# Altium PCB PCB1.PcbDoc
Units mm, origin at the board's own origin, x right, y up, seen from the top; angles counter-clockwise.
Board outline 50 x 50 mm, 2 copper layers (Top Layer, Bottom Layer); 47 components, 35 nets, 150 pads, 6 vias.
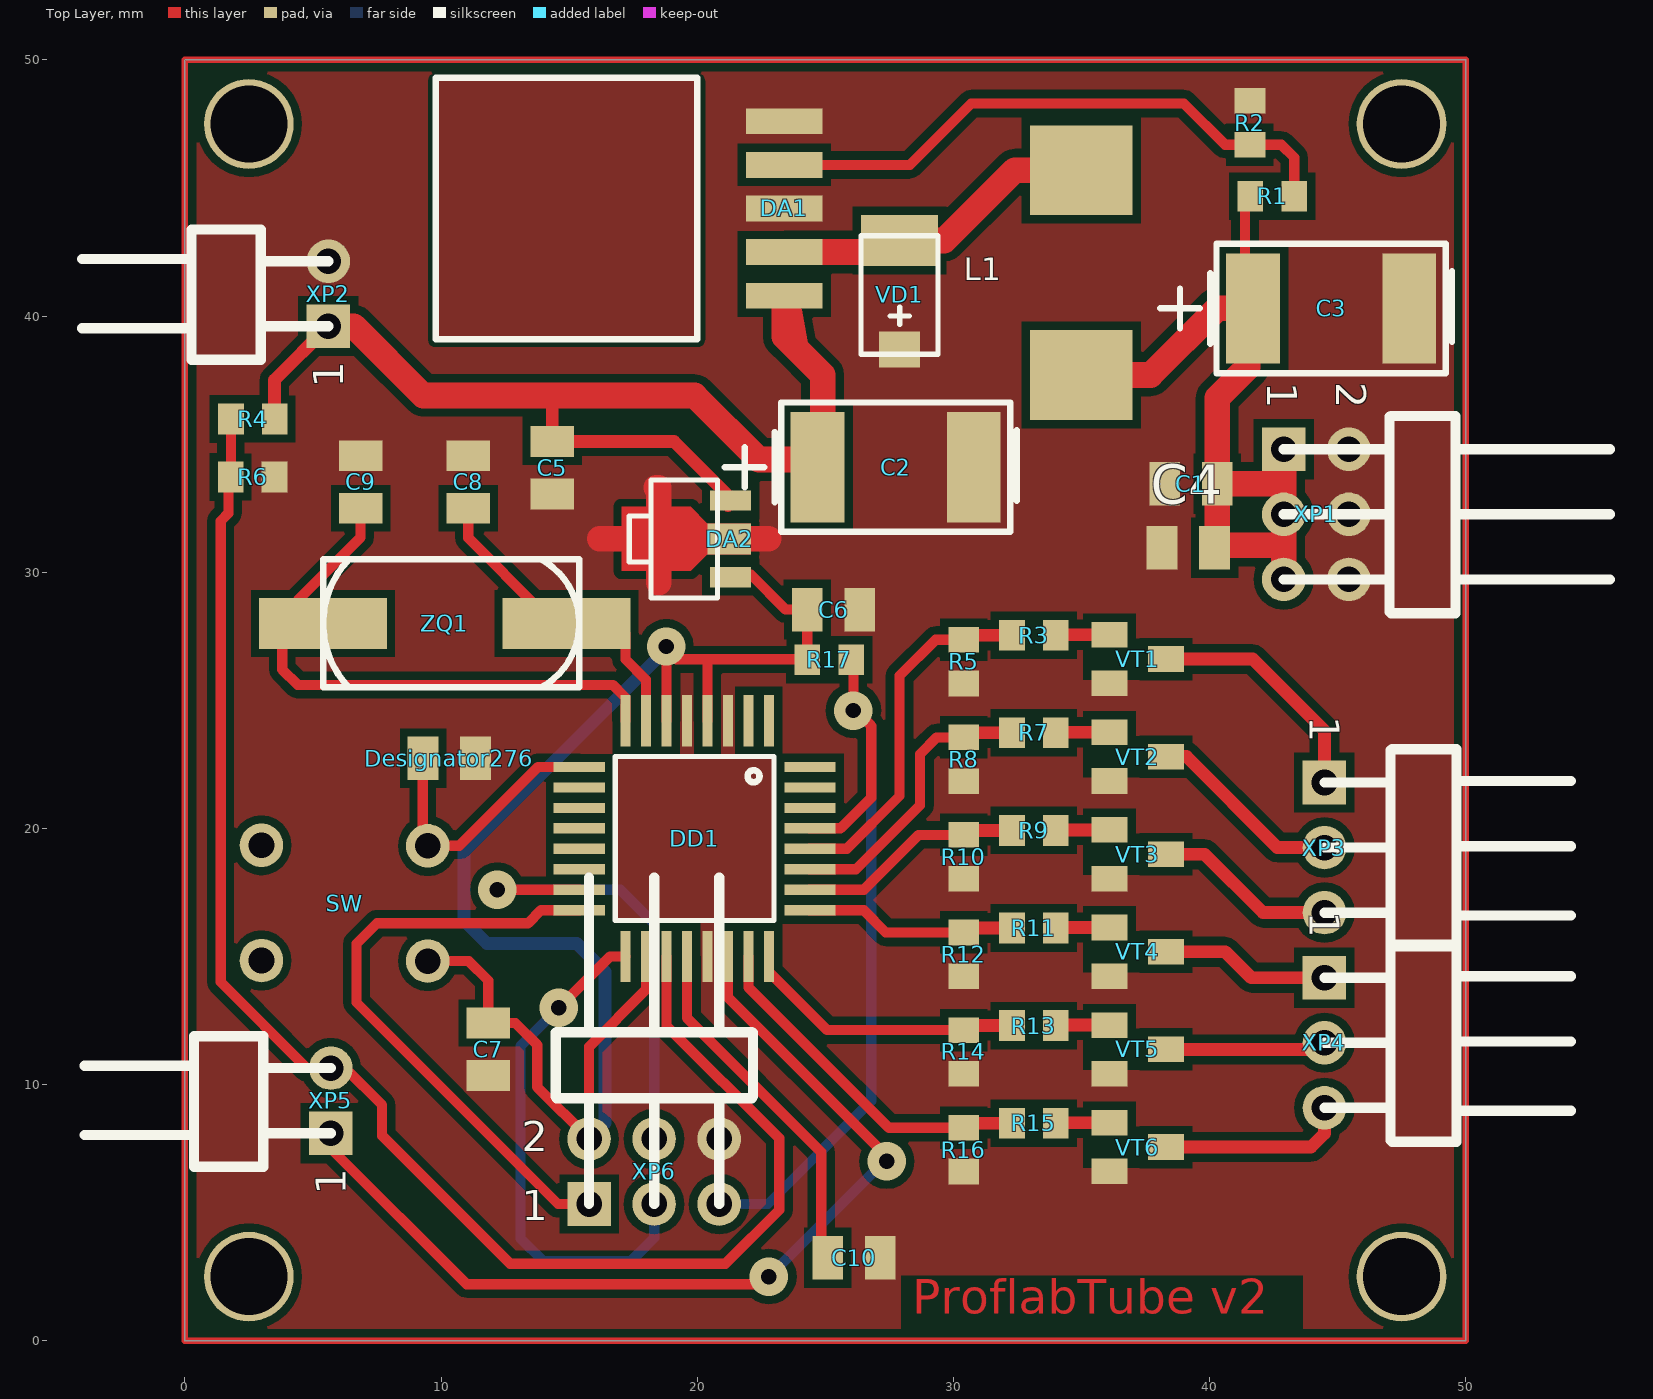
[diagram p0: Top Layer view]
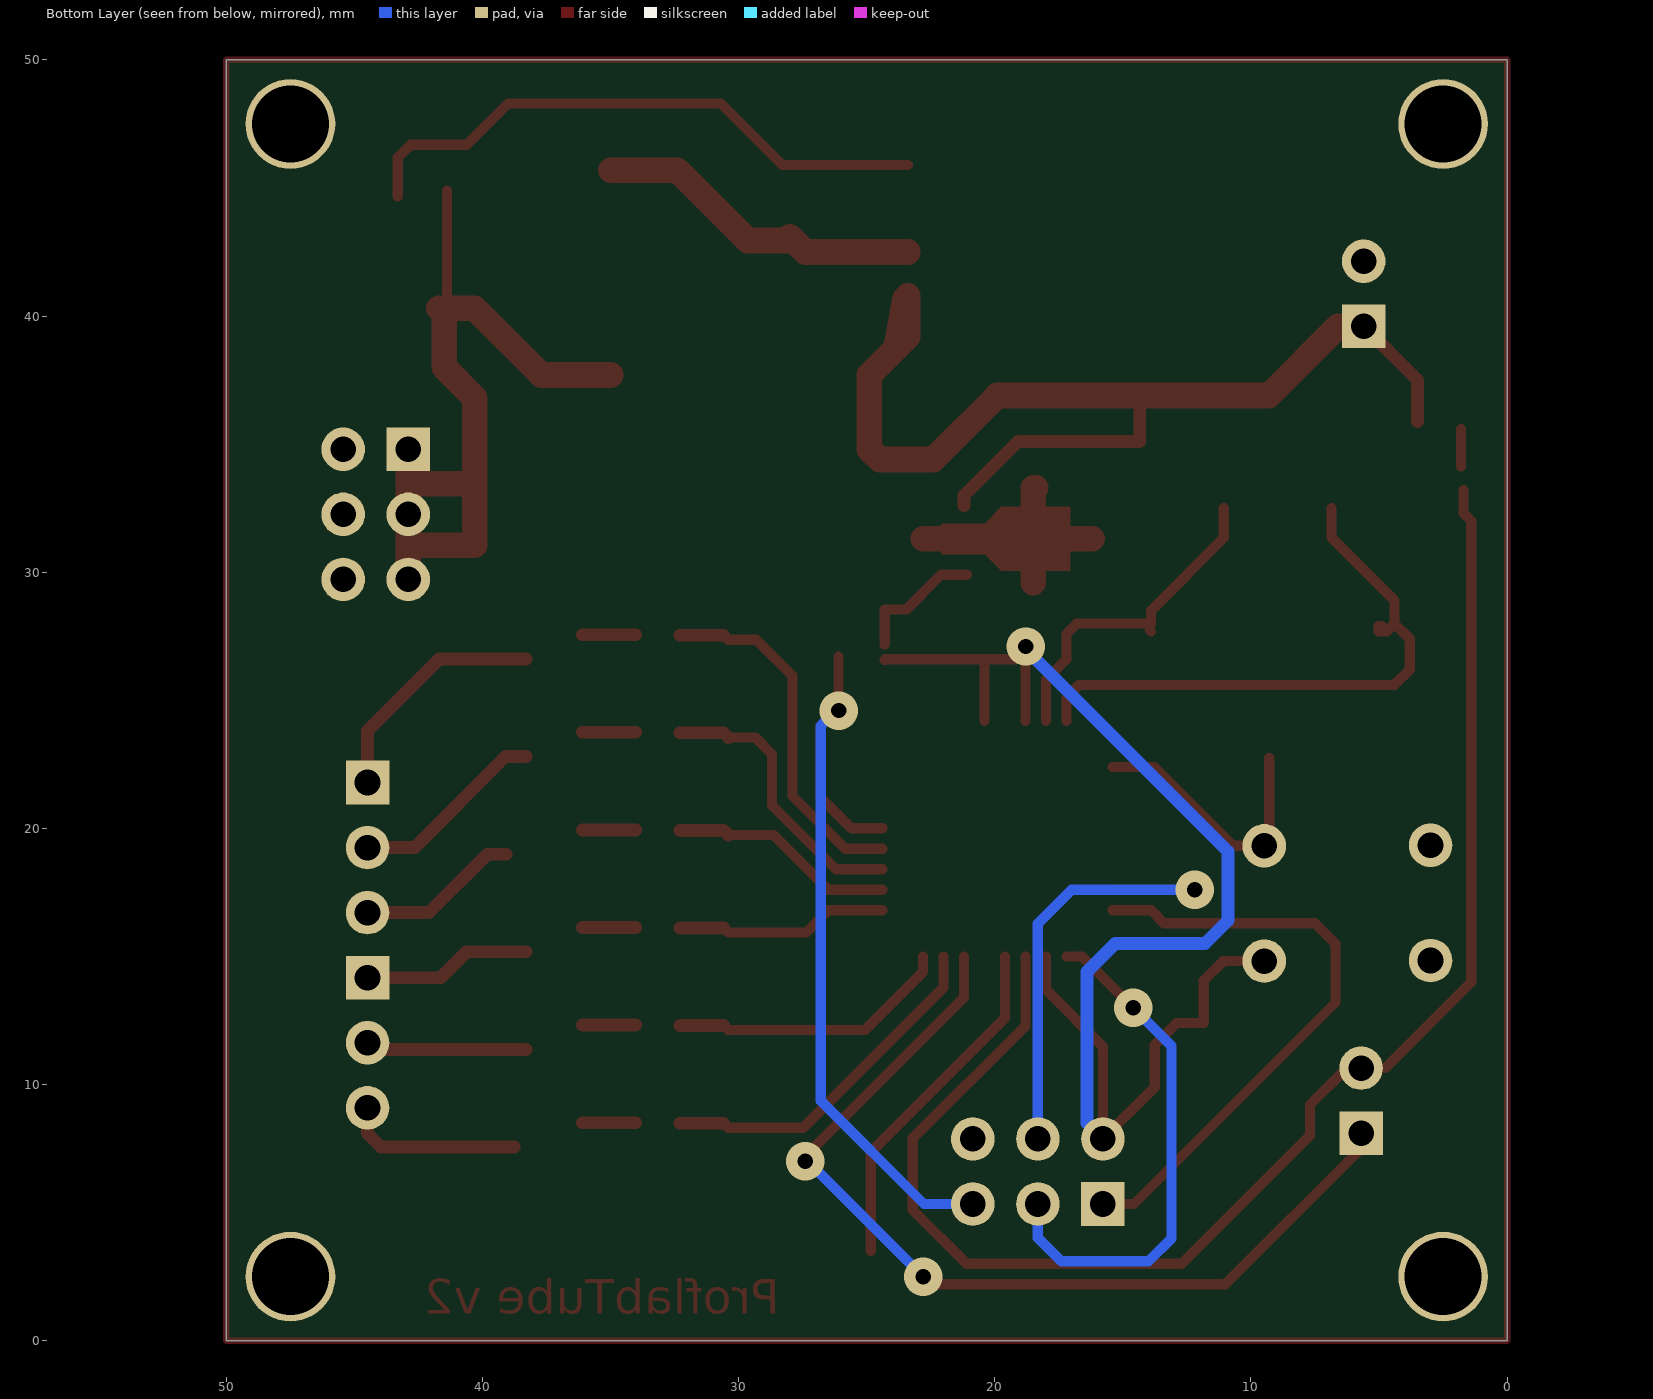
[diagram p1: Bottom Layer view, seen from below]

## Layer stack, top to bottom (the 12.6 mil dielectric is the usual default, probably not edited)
Top Layer: signal copper 0.0356
Dielectric: dielectric 0.32, FR-4, Dk 4.8
Bottom Layer: signal copper 0.0356

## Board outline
0,0 50,0 50,50 0,50

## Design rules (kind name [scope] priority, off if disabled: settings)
Clearance [All] p1: gap=0.32
PolygonConnect PolygonConnect_1 [All vs IsNamedPolygon('Top Layer-No Net')] p1: connectstyle=Direct reliefconductorwidth=0.254 reliefentries=4 polygonreliefangle="90 Angle" airgapwidth=0.254
PolygonConnect [All] p2: connectstyle=Relief reliefconductorwidth=0.254 reliefentries=4 polygonreliefangle="90 Angle" airgapwidth=0.254
RoutingVias [All] p1: holewidth=0.711 width=1.7 viastyle="Through Hole" minholewidth=0.711 minwidth=1.27 maxholewidth=0.711 maxwidth=1.27
SilkscreenOverComponentPads [All] p1: minsilkscreentomaskgap=0.254
SolderMaskExpansion [All] p1: expansion=0.102
Width [All] p1: maxlimit=1 minlimit=0.25 preferedwidth=0.3
27 further rules are at their usual default settings.

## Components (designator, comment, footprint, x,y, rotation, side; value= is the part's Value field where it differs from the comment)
C1 "C0805" SMD0805 40.3,33.4 r180 top
C2 "TAJ_SMD_E" FT-SMD-E 24.7,34.1 r0 top
C3 "TAJ_SMD_E" FT-SMD-E 41.7,40.3 r0 top
C4 "C0805" SMD0805 40.2,30.9 r180 top
C5 "C0805" SMD0805 14.4,35.1 r270 top
C6 "C0805" SMD0805 24.3,28.6 r0 top
C7 "C0805" SMD0805 11.9,12.4 r270 top
C8 "C0805" SMD0805 11,32.5 r90 top
C9 "C0805" SMD0805 6.8,32.5 r90 top
C10 "C0805" SMD0805 25.1,3.3 r0 top
DA1 "LM2576" "TO_220-5 smd" 23.4,40.8 r90 top
DA2 "TA78L05_F" SOT-89 21.3,29.8 r90 top
DD1 "ATmega328" Quad32 22.8,24.2 r270 top
Designator276 "Comment" SMD0805 9.3,22.8 r0 top
L1 "Comment" 7443552560 35,41.7 r90 top
R1 "R0603" SMD0603 41.6,44.7 r0 top
R2 "R0603" SMD0603 41.6,48.4 r270 top
R3 "R0603" SMD0603 32.29,27.56 r0 top
R4 "R0603" SMD0603 1.8,36 r0 top
R5 "R0603" SMD0603 30.385,25.655 r90 top
R6 "R0603" SMD0603 3.5,33.7 r180 top
R7 "R0603" SMD0603 32.29,23.75 r0 top
R8 "R0603" SMD0603 30.385,21.845 r90 top
R9 "R0603" SMD0603 32.29,19.94 r0 top
R10 "R0603" SMD0603 30.385,18.035 r90 top
R11 "R0603" SMD0603 32.29,16.13 r0 top
R12 "R0603" SMD0603 30.385,14.225 r90 top
R13 "R0603" SMD0603 32.29,12.32 r0 top
R14 "R0603" SMD0603 30.385,10.415 r90 top
R15 "R0603" SMD0603 32.29,8.51 r0 top
R16 "R0603" SMD0603 30.385,6.605 r90 top
R17 "R0603" SMD0603 24.3,26.6 r0 top
SW "Comment" "PT65-102 - duplicate" 6.8,16.8 r0 top
VD1 "10MQ040N" SMA 27.9,38.7 r90 top
VT1 "FDV303N" SOT23_FDV303N 37.2,26.61 r90 top
VT2 "FDV303N" SOT23_FDV303N 37.2,22.8 r90 top
VT3 "FDV303N" SOT23_FDV303N 37.2,18.99 r90 top
VT4 "FDV303N" SOT23_FDV303N 37.2,15.18 r90 top
VT5 "FDV303N" SOT23_FDV303N 37.2,11.37 r90 top
VT6 "FDV303N" SOT23_FDV303N 37.2,7.56 r90 top
XP1 "PLD_6R" PLD_6R 42.9,34.8 r270 top
XP2 "PLS_2R" PLS_2R 5.6,39.6 r90 top
XP3 "PLS_3R" PLS_3R 44.49,21.79 r270 top
XP4 "PLS_3R" PLS_3R 44.49,14.17 r270 top
XP5 "PLS_2R" PLS_2R 5.7,8.1 r90 top
XP6 "PLD_6R" PLD_6R 15.78,5.335 r0 top
ZQ1 "ZQ" HC49SM 5.4,28 r0 top

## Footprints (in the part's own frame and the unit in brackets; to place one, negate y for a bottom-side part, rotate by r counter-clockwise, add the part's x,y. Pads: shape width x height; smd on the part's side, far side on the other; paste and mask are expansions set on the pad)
7443552560 [mm]
  rect 3.5x4 smd: 1(-4,0) 2(4,0)
FT-SMD-E [mm]
  rect 2.1x4.3 smd: 1(0,0) 2(6.1,0)
  silkscreen extent -3.62,-2.53 7.77,2.53
HC49SM [mm]
  rect 5x2 smd: 1(0,0) 2(9.5,0)
  silkscreen extent 0,-2.5 10,2.5
PLD_6R [mm]
  rect 1.7x1.7 hole 1: 1(0,0)
  round 1.7 hole 1: 2(0,2.54) 3(2.54,0) 4(2.54,2.54) 5(5.08,0) 6(5.08,2.54)
  silkscreen extent -1.3,0 6.4,12.74
PLS_2R [mm]
  rect 1.7x1.7 hole 1: 1(0,0)
  round 1.7 hole 1: 2(2.54,0)
  silkscreen extent -1.31,0 3.78,9.62
PLS_3R [mm]
  rect 1.7x1.7 hole 1: 1(0,0)
  round 1.7 hole 1: 2(2.54,0) 3(5.08,0)
  silkscreen extent -1.3,0 6.4,9.62
"PT65-102 - duplicate" [mm]
  round 1.7 hole 1: 1(-3.81,2.54) 2(-3.81,-1.96) 3(2.682,-1.982) 4(2.682,2.518)
Quad32 [mm]
  rect 2x0.4 smd: 1(0,0) 2(0,-0.8) 3(0,-1.6) 4(0,-2.4) 5(0,-3.2) 6(0,-4) 7(0,-4.8) 8(0,-5.6) 17(9.2,-5.6) 18(9.2,-4.8) 19(9.2,-4) 20(9.2,-3.2) 21(9.2,-2.4) 22(9.2,-1.6) 23(9.2,-0.8) 24(9.2,0)
  rect 0.4x2 smd: 9(1.8,-7.4) 10(2.6,-7.4) 11(3.4,-7.4) 12(4.2,-7.4) 13(5,-7.4) 14(5.8,-7.4) 15(6.6,-7.4) 16(7.4,-7.4) 25(7.4,1.6) 26(6.6,1.6) 27(5.8,1.6) 28(5,1.6) 29(4.2,1.6) 30(3.4,1.6) 31(2.6,1.6) 32(1.8,1.6)
  silkscreen extent 1.4,-6 7.8,0.2
SMA [mm]
  rect 1.4x1.6 smd: 1(0,0)
  rect 2x3 smd: 2(4.25,0)
  silkscreen extent -0.19,-1.5 4.44,1.5
SMD0603 [mm]
  rect 1x1.2 smd: 1(0,-0.02) 2(1.71,-0.02)
SMD0805 [mm]
  rect 1.2x1.7 smd: 1(0,-0.06) 2(2.05,-0.06)
SOT23_FDV303N [mm]
  rect 1x1.4 smd: D(0,-1.1) G(0.95,1.1) S(-0.95,1.1)
  Top Layer pour cut-out: -0.8,-0.5 -0.8,2.125 0.8,2.125 0.8,-0.5
SOT-89 [mm]
  rect 0.8x1.6 smd: 1(0,0) 3(3,0)
  rect 1.2x1.7 smd: 2(1.5,0.05)
  Top Layer region: 2.1,-0.8 2.1,0.9 2.75,1.55 2.75,4.25 0.25,4.25 0.25,1.55 0.9,0.9 0.9,-0.8
  silkscreen extent -0.8,0.5 3.8,3.95
"TO_220-5 smd" [mm]
  rect 1x3 smd: 1(0,0) 2(1.7,0) 3(3.4,0) 4(5.1,0) 5(6.8,0)
  silkscreen extent -1.7,3.4 8.5,13.6

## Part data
VT1 VT2 VT3 VT4 VT5 VT6: "IGFET(P)"

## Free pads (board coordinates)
  round 3.5 hole 3: 4(2.5,2.5) 4(2.5,47.5) 4(47.5,2.5) 4(47.5,47.5)

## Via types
v1: diameter 1.5, hole 0.6, Top Layer to Bottom Layer, 6 vias

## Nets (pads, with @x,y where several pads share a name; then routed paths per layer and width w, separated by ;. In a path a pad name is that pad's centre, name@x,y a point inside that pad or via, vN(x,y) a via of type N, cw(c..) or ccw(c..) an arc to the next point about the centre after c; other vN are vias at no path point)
1: DD1.9 Designator276.1 SW.4 | length 10.8
  Top Layer w0.4: Designator276.1@9.282,22.74 9.282,19.318 SW.4 10.718,19.318 13.8,22.4 DD1.9
2: 
+5V: C6.1 C7.1 DA2.1 DD1.4 DD1.6 DD1.18 R17.1 SW.3 XP6.2 | length 63
  Top Layer w0.4: SW.3@9.282,14.818 SW.3 11.082,14.818 11.84,14.06 C7.1 12.9,12.4 13.755,11.545 13.755,9.9 XP6.2 15.78,11.48 18,13.7 DD1.18 ; v1@18.7,27.1 18.75,27.05 v1@18.85,26.95 ; DD1.6 18.8,26.9 v1@18.85,26.95 ; v1@19.08,27.18 v1@18.85,26.95 ; DD1.4 20.4,26.6 ; DA2.1@21.1,29.9 22.1,29.9 23.46,28.54 C6.1 24.3,27.18 ; R17.1 24.28,26.6 20.4,26.6 ; v1@18.85,26.95 19.2,26.6 20.4,26.6
  Bottom Layer w0.5: XP6.2 16.4,8.495 16.4,14.4 15.3,15.5 11.8,15.5 10.9,16.4 10.9,19.1 18.8,27 v1(18.8,27.1) v1@18.8,27.2
GND: C1.2 C2.2 C3.2 C4.2 C5.2 C6.2 C7.2 C8.2 C9.2 C10.2 DA1.3 DA1.5 DA2.2 DD1.3 DD1.5 DD1.21 Designator276.2 R2.1 R5.1 R6.1 R8.1 R10.1 R12.1 R14.1 R16.1 VD1.1 VT1.S VT2.S VT3.S VT4.S VT5.S VT6.S XP1.2 XP1.4 XP1.6 XP2.2 XP6.6 | length 7.6
  Top Layer w1: 16.2,31.3 18.5,31.3 ; 18.4,33.3 18.5,33.3 18.5,29.6 ; DA2.2 22.8,31.3
NetC1_1: C1.1 C3.1 C4.1 L1.1 R1.1 XP1.1 XP1.3 XP1.5 | length 32.3
  Top Layer w0.4: C3.1@41.39,40.41 R1.1@41.39,44.9
  Top Layer w0.5: 42.86,31.06 42.9,31.1
  Top Layer w1: L1.1 37.7,37.7 40.3,40.3 C3.1 ; C3.1@41.5,40.3 41.5,38 40.3,36.8 C1.1 ; 42.86,31.06 40.3,31.06 C1.1 ; 42.86,33.46 C1.1 ; XP1.5 42.9,31.1 XP1.3 XP1.1
NetC2_1: C2.1 C5.1 DA1.1 DA2.3 R4.2 XP2.1 | length 44.5
  Top Layer w0.5: R4.2@3.5,35.88 3.5,37.5 XP2.1 ; 14.3,36.9 14.34,36.86 C5.1 19.1,35.1 21.2,33 DA2.3@21.2,32.6
  Top Layer w1: XP2.1 6.6,39.6 9.3,36.9 14.3,36.9 19.9,36.9 22.4,34.4 C2.1@24.5,34.4 ; DA1.1 23.4,39.2 23.845,38.755 ; DA1.1@23.5,40.7 23.845,38.755 ; C2.1@24.65,34.55 24.9,34.8 24.9,37.7 23.845,38.755
NetC8_1: C8.1 DD1.7 ZQ1.2 | length 12.9
  Top Layer w0.4: C8.1 11.06,31.34 13.9,28.5 13.9,28 ZQ1.2 16.8,28 17.2,27.6 17.2,26.6 18,25.8 DD1.7 ; ZQ1.2@13.9,27.7 ZQ1.2@13.93,27.73
NetC9_1: C9.1 DD1.8 ZQ1.1 | length 23.7
  Top Layer w0.4: C9.1 6.86,31.36 4.4,28.9 ZQ1.1@4.4,28 ; DD1.8 17.2,25.1 16.7,25.6 4.4,25.6 3.8,26.2 3.8,27.4 ZQ1.1@4.4,28 ; ZQ1.1@4.4,28 ZQ1.1@4.7,27.7 ; ZQ1.1@4.7,27.7 4.9,27.9 5.026,27.9 5.026,27.7 ZQ1.1@4.7,27.7
NetC10_1: C10.1 DD1.20 | length 13.7
  Top Layer w0.4: DD1.20 19.6,12.6 24.84,7.36 C10.1@24.84,3.5
NetDA1_2: DA1.2 L1.2 VD1.2 | length 13.1
  Top Layer w1: DA1.2 27.4,42.5 VD1.2@28,43.1 ; VD1.2 29.65,42.95 32.4,45.7 L1.2
NetDA1_4: DA1.4 R1.2 R2.2 | length 23.3
  Top Layer w0.4: DA1.4 28.3,45.9 30.7,48.3 39,48.3 40.61,46.69 R2.2 42.81,46.69 43.31,46.19 R1.2
NetDD1_15: DD1.15 XP6.4 | length 18.4
  Top Layer w0.4: v1@12.1,17.6 v1(12.2,17.6) DD1.15
  Bottom Layer w0.4: v1(12.2,17.6) 17,17.6 18.32,16.28 XP6.4
NetDD1_16: DD1.16 XP6.1 | length 23.9
  Top Layer w0.4: DD1.16 13.9,16.8 13.4,16.3 7.5,16.3 6.7,15.5 6.7,13.2 14.565,5.335 XP6.1
NetDD1_17: DD1.17 XP6.3 | length 20.3
  Top Layer w0.4: v1(14.6,13) 16.6,15 DD1.17
  Bottom Layer w0.4: v1(14.6,13) 13.1,11.5 13.1,4 14,3.1 17.4,3.1 18.32,4.02 XP6.3
NetDD1_19: DD1.19 R4.1 R6.2 XP5.2 | length 60.4
  Top Layer w0.4: R6.2@1.7,33.2 1.7,32.3 1.4,32 1.4,14 4.76,10.64 XP5.2 6.26,10.64 7.7,9.2 7.7,8 12.7,3 21.1,3 23.2,5.1 23.2,7.9 18.8,12.3 DD1.19 ; R6.2@1.8,34.13 R4.1@1.8,35.58
NetDD1_22: DD1.22 XP5.1 | length 37.5
  Top Layer w0.4: XP5.1 5.7,7.5 11,2.2 22.5,2.2 v1(22.8,2.5) ; DD1.22 21.2,13.4 27.4,7.2 v1(27.4,7) v1@27.4,6.6
  Bottom Layer w0.4: v1(22.8,2.5) v1@27.4,7.1
NetDD1_23: DD1.23 R15.1 R16.2 | length 13.6
  Top Layer w0.4: DD1.23 22,13.8 27.485,8.315 R16.2
  Top Layer w0.5: R16.2@30.58,8.49 R15.1
NetDD1_24: DD1.24 R13.1 R14.2 | length 10.9
  Top Layer w0.4: DD1.24 22.8,14.4 25.075,12.125 R14.2
  Top Layer w0.5: R14.2@30.58,12.3 R13.1
NetDD1_25: DD1.25 R11.1 R12.2 | length 8.1
  Top Layer w0.4: DD1.25 26.5,16.8 27.365,15.935 R12.2
  Top Layer w0.5: R12.2@30.58,16.11 R11.1
NetDD1_26: DD1.26 R9.1 R10.2 | length 8.9
  Top Layer w0.4: DD1.26 26.5,17.6 28.645,19.745 R10.2
  Top Layer w0.5: R10.2 30.58,19.92 R9.1
NetDD1_27: DD1.27 R7.1 R8.2 | length 11
  Top Layer w0.4: DD1.27 26.2,18.4 28.7,20.9 28.7,22.9 29.35,23.55 R8.2@30.4,23.55
  Top Layer w0.5: R8.2@30.4,23.55 R8.2 ; R8.2@30.58,23.73 R7.1
NetDD1_28: DD1.28 R3.1 R5.2 | length 13.8
  Top Layer w0.4: DD1.28 25.835,19.2 27.9,21.265 27.9,25.955 29.31,27.365 R5.2
  Top Layer w0.5: R5.2@30.58,27.54 R3.1
NetDD1_29: DD1.29 R17.2 XP6.5 | length 31.9
  Top Layer w0.4: DD1.29 25.6,20 26.8,21.2 26.8,24 26.2,24.6 v1(26.1,24.6) R17.2@26.1,26.7
  Bottom Layer w0.4: XP6.5 22.765,5.335 26.8,9.37 26.8,24 26.2,24.6 v1(26.1,24.6)
NetR3_2: R3.2 VT1.G | length 2.1
  Top Layer w0.5: R3.2@34.02,27.56 VT1.G
NetR7_2: R7.2 VT2.G | length 2.1
  Top Layer w0.5: R7.2@34.02,23.75 VT2.G
NetR9_2: R9.2 VT3.G | length 2.1
  Top Layer w0.5: R9.2@34.02,19.94 VT3.G
NetR11_2: R11.2 VT4.G | length 2.1
  Top Layer w0.5: R11.2@34.02,16.13 VT4.G
NetR13_2: R13.2 VT5.G | length 2.1
  Top Layer w0.5: R13.2@34.02,12.32 VT5.G
NetR15_2: R15.2 VT6.G | length 2.1
  Top Layer w0.5: R15.2@34.02,8.51 VT6.G
NetVT1_D: VT1.D XP3.1 | length 9.4
  Top Layer w0.5: VT1.D 41.69,26.61 44.49,23.81 XP3.1
NetVT2_D: VT2.D XP3.2 | length 7.7
  Top Layer w0.5: VT2.D 39.1,22.8 42.65,19.25 XP3.2
NetVT3_D: VT3.D XP3.3 | length 6.3
  Top Layer w0.5: 39.09,18.99 39.81,18.99 42.09,16.71 XP3.3
NetVT4_D: VT4.D XP4.1 | length 6.6
  Top Layer w0.5: VT4.D 40.62,15.18 41.63,14.17 XP4.1
NetVT5_D: VT5.D XP4.2 | length 6.3
  Top Layer w0.5: VT5.D 44.23,11.37 XP4.2
NetVT6_D: VT6.D XP4.3 | length 7.1
  Top Layer w0.5: VT6.D@38.76,7.56 43.96,7.56 44.49,8.09 XP4.3 XP4.3@44.29,9.09
pads on no net: DD1.1 DD1.2 DD1.10 DD1.11 DD1.12 DD1.13 DD1.14 DD1.30 DD1.31 DD1.32 SW.1 SW.2
copper on no net: | length 200
  Top Layer w0.254: 0,0 0,50 50,50 50,0 0,0

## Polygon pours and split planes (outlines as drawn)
no net on Top Layer "Top Layer-No Net" (solid, pour order 6): 9.8,49.2 9.8,39.1 20,39.1 20,49.2
GND on Top Layer "Top Layer-No Net" (solid, remove dead copper, pour order 2): 0.1,49.9 0,49.8 0,0.2 49.8,0.2 50.3,-0.3 49.8,0.2 49.8,49.9

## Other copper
Top Layer:
  text "ProflabTube v2" at 28.4,0.6 h2.3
